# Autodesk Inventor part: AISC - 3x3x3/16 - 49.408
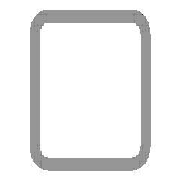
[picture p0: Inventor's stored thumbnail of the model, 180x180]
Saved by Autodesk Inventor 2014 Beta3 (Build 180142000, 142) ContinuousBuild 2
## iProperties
IsCustomPart: 1
Created: 2011-01
Part Number: AISC - 3x3x3/16 - 49.408
Material: Steel, Mild
Description: Tube
Document SubType Name: Modeling
Standard: ANSI
Designer: Beta-8540w
Standards Organization: ANSI
Language: en-US
Size Designation: 3x3x3/16
Categories: <MemberInstance><Categories><Category DisplayName="Structural Shapes" InternalName="089c4875-fa83-4c05-b084-43b9cc11f5ed" Mnemonic="GRDR"><CategoryParameter Dis
Stock Number: 3x3x3/16
Density: 7.86 g/cm^3
Appearance: Steel
G_L: 49.408 in
G_W: 3.000 in
G_H: 3.000 in
+F48483C9-E9F5-4C3B-A2E0-95EBE26CBBEF+CUTDETAIL1: Miter 45.00 deg
_CCFamilyMember: 9
_CCFamilyDisplayName: ANSI AISC (Square) - Tube
_FrameMemberDoc: Frame Member File
_Version: 15.0.0
_GetPNFromCC: 1
Author: Beta-8540w
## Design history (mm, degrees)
node "Start plane"
node "End plane"
sketch "Sketch"
  geometry: L1 (-38.1, -28.575)-(-38.1, 28.575); L2 (-28.575, 38.1)-(28.575, 38.1); L3 (38.1, 28.575)-(38.1, -28.575); L4 (28.575, -38.1)-(-28.575, -38.1); L5 (-28.575, 33.337)-(28.575, 33.338); L6 (33.338, 28.575)-(33.338, -28.575); L7 (28.575, -33.337)-(-28.575, -33.338); L8 (-33.338, -28.575)-(-33.338, 28.575); L9 (0, 56.102)-(0, -56.102) reference; L10 (-56.102, 0)-(56.102, 0) reference; A1 r 9.525 centre (-28.575, -28.575) between (-38.1, -28.575) and (-28.575, -38.1); A2 r 9.525 centre (-28.575, 28.575) between (-28.575, 38.1) and (-38.1, 28.575); A3 r 9.525 centre (28.575, 28.575) between (38.1, 28.575) and (28.575, 38.1); A4 r 9.525 centre (28.575, -28.575) between (28.575, -38.1) and (38.1, -28.575); A5 r 4.763 centre (-28.575, 28.575) between (-28.575, 33.337) and (-33.338, 28.575); A6 r 4.763 centre (28.575, 28.575) between (33.338, 28.575) and (28.575, 33.338); A7 r 4.763 centre (28.575, -28.575) between (28.575, -33.337) and (33.338, -28.575); A8 r 4.763 centre (-28.575, -28.575) between (-33.338, -28.575) and (-28.575, -33.338)
  constraints: 16 end point, 16 point on circle, 8 centre point, 8 tangent, 4 parallel, 3 equal radius, 2 perpendicular, 7 other
  dimensions: "d10" = 76.2 distance between parallel lines of L2 L4 (= G_H); "d11" = 76.2 distance between parallel lines of L1 L3 (= G_W); "d12" = 4.7625 distance between parallel lines of L3 L6 (= G_T); "d15" = 38.1 distance between parallel lines of L2 L10 (= 0.5 x d10); "d16" = 38.1 distance between parallel lines of L9 L3 (= 0.5 x d11); "d17" = 9.525 radius of A1 (= G_IR)
extrude "Body" new body sketch "Sketch" stored distance "d3" = 1254.96513 (= G_L); taper "d4" = 0 deg
node "Driven Length"
  sketch "Sketch3"
    geometry: L1 (0, 0)-(10, 0) reference
    constraints: 2 end point, 1 horizontal
  workplane "Work Plane3"
  sketch "Sketch4"
    geometry: L1 (-2, -35.765)-(12, -35.765) reference; L2 (-2, 1219.2)-(12, 1219.2) reference
    dimensions: "d19" = 1254.96513 distance between parallel lines of L1 L2 (derived)
workplane "Work Plane4"
split "Split1"
body "Solid1"
other parameters: "G_W" = 76.2 [user parameter; used in 1 equation term], "G_H" = 76.2 [user parameter; used in 1 equation term], "G_T" = 4.7625 [user parameter; used in 1 equation term], "G_IR" = 9.525 [user parameter; used in 1 equation term], "G_L" = 1254.96513 (= d19) [user parameter; used in 1 equation term], "G_OFFSET_START" = 35.76513 [user parameter; used in 1 equation term], "G_OFFSET_END" = 0 [user parameter; used in 1 equation term], "d13" = -35.76513 (= -G_OFFSET_START), "d14" = 1219.2 (= G_OFFSET_END + B_L), "B_L" = 1219.2 [user parameter; used in 1 equation term], "d18" = 90 deg
